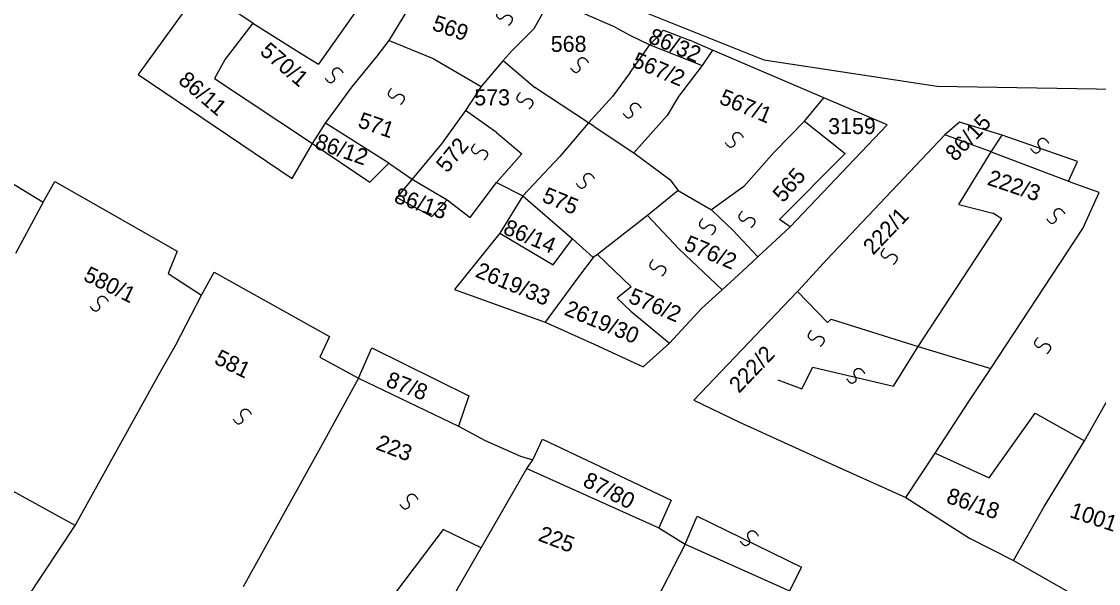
# Model space of a CAD drawing. Extents: x -581999 to -572728, y -1219553 to -1212032.
# Drawn here: x -578208.2 to -578073.6, y -1215797.5 to -1215727.3 of the extents above; entities that cross this region are included whole.
import ezdxf

# ---------------------------------------------------------------- set-up
doc = ezdxf.new("R2010")
doc.units = 0
for name, color, linetype in [('Vrstva 1', 7, 'Continuous'), ('Vrstva 2', 7, 'Continuous'), ('Vrstva 4', 7, 'Continuous'), ('Vrstva 6', 7, 'Continuous')]:
    doc.layers.add(name, color=color, linetype=linetype)

msp = doc.modelspace()

# ---------------------------------------------------------------- linework, layer by layer
at = {"layer": 'Vrstva 1'}
for p, q in [((-578129.628, -1215730.267), (-578123.109, -1215732.832)), ((-578110.331, -1215739.79), (-578105.22, -1215743.817)), ((-578090.935, -1215739.913), (-578092.767, -1215741.49)), ((-578085.613, -1215741.548), (-578090.935, -1215739.913)), ((-578086.985, -1215743.633), (-578085.613, -1215741.548)), ((-578105.22, -1215743.817), (-578113.434, -1215752.056)), ((-578086.985, -1215743.633), (-578077.316, -1215747.275)), ((-578159.362, -1215747.04), (-578161.259, -1215749.31)), ((-578077.005, -1215747.454), (-578077.316, -1215747.275)), ((-578073.5, -1215748.699), (-578077.005, -1215747.454)), ((-578161.259, -1215749.31), (-578156.879, -1215751.69)), ((-578156.879, -1215751.69), (-578154.984, -1215749.617)), ((-578112.091, -1215752.975), (-578113.434, -1215752.056)), ((-578141.728, -1215757.732), (-578139.322, -1215754.499)), ((-578120.615, -1215760.835), (-578118.072, -1215758.514)), ((-578123.156, -1215763.155), (-578120.615, -1215760.835))]:
    msp.add_line(p, q, dxfattribs=at)
for points in [[(-578162.225, -1215729.695), (-578156.331, -1215720.016), (-578155.486, -1215718.447)], [(-578162.583, -1215720.673), (-578171.062, -1215732.648)], [(-578185.669, -1215723.015), (-578193.603, -1215733.96), (-578174.349, -1215746.938), (-578171.804, -1215742.588)], [(-578137.475, -1215723.258), (-578115.402, -1215732.134), (-578093.726, -1215735.415), (-578046.398, -1215736.187), (-578004.439, -1215735.994)], [(-578142.053, -1215724.498), (-578144.151, -1215728.248)], [(-578133.982, -1215728.039), (-578142.053, -1215724.498)], [(-578179.251, -1215727.542), (-578182.684, -1215725.277)], [(-578179.251, -1215727.542), (-578182.693, -1215732.039)], [(-578179.251, -1215727.542), (-578173.1, -1215731.412)], [(-578144.151, -1215728.248), (-578146.843, -1215730.943)], [(-578133.982, -1215728.039), (-578132.14, -1215729.047)], [(-578129.628, -1215730.267), (-578127.922, -1215728.4), (-578124.701, -1215729.677)], [(-578163.722, -1215731.645), (-578162.225, -1215729.695)], [(-578162.225, -1215729.695), (-578156.702, -1215731.966)], [(-578132.14, -1215729.047), (-578129.628, -1215730.267)], [(-578121.829, -1215730.932), (-578124.701, -1215729.677)], [(-578173.1, -1215731.412), (-578171.062, -1215732.648)], [(-578146.843, -1215730.943), (-578147.987, -1215732.225)], [(-578132.109, -1215733.702), (-578129.628, -1215730.267)], [(-578121.829, -1215730.932), (-578123.109, -1215732.832), (-578126.068, -1215736.713)], [(-578107.882, -1215736.864), (-578121.829, -1215730.932)], [(-578182.693, -1215732.039), (-578184.042, -1215734.439), (-578171.804, -1215742.588)], [(-578166.865, -1215735.542), (-578163.722, -1215731.645)], [(-578156.702, -1215731.966), (-578150.733, -1215735.439)], [(-578147.987, -1215732.225), (-578150.733, -1215735.439)], [(-578147.987, -1215732.225), (-578144.017, -1215735.57)], [(-578132.109, -1215733.702), (-578134.309, -1215736.689)], [(-578150.733, -1215735.439), (-578152.68, -1215738.437)], [(-578170.157, -1215740.039), (-578166.865, -1215735.542)], [(-578137.3, -1215739.985), (-578144.017, -1215735.57)], [(-578134.309, -1215736.689), (-578137.3, -1215739.985)], [(-578126.068, -1215736.713), (-578127.498, -1215739.067)], [(-578114.109, -1215743.664), (-578110.331, -1215739.79), (-578107.882, -1215736.864)], [(-578112.091, -1215752.975), (-578099.977, -1215740.245), (-578107.882, -1215736.864)], [(-578152.68, -1215738.437), (-578155.673, -1215742.635)], [(-578148.791, -1215741.221), (-578152.68, -1215738.437)], [(-578127.498, -1215739.067), (-578131.633, -1215743.757)], [(-578171.804, -1215742.588), (-578170.157, -1215740.039)], [(-578162.248, -1215745.019), (-578170.157, -1215740.039)], [(-578137.3, -1215739.985), (-578140.891, -1215744.18)], [(-578136.603, -1215740.448), (-578137.3, -1215739.985)], [(-578136.603, -1215740.448), (-578131.633, -1215743.757)], [(-578148.791, -1215741.221), (-578145.636, -1215743.845), (-578148.811, -1215747.462)], [(-578092.767, -1215741.49), (-578107.532, -1215757.067)], [(-578086.985, -1215743.633), (-578092.767, -1215741.49)], [(-578171.804, -1215742.588), (-578164.642, -1215747.416), (-578162.248, -1215745.019)], [(-578155.673, -1215742.635), (-578159.362, -1215747.04)], [(-578140.891, -1215744.18), (-578145.528, -1215749.124)], [(-578131.633, -1215743.757), (-578127.159, -1215747.075)], [(-578117.886, -1215747.959), (-578114.109, -1215743.664)], [(-578091.025, -1215750.209), (-578086.985, -1215743.633)], [(-578162.248, -1215745.019), (-578159.362, -1215747.04)], [(-578209.608, -1215747.342), (-578205.477, -1215749.921)], [(-578205.477, -1215749.921), (-578203.992, -1215747.315), (-578188.712, -1215756.026), (-578189.828, -1215758.818)], [(-578159.362, -1215747.04), (-578154.984, -1215749.617)], [(-578154.984, -1215749.617), (-578152.104, -1215751.809), (-578148.811, -1215747.462)], [(-578148.811, -1215747.462), (-578145.528, -1215749.124)], [(-578127.159, -1215747.075), (-578126.116, -1215748.429)], [(-578126.116, -1215748.429), (-578129.943, -1215751.552)], [(-578126.116, -1215748.429), (-578121.94, -1215750.844)], [(-578117.886, -1215747.959), (-578121.94, -1215750.844)], [(-578075.523, -1215753.171), (-578073.5, -1215748.699)], [(-578205.477, -1215749.921), (-578208.899, -1215756.332)], [(-578145.528, -1215749.124), (-578148.373, -1215753.772)], [(-578145.528, -1215749.124), (-578139.322, -1215754.499)], [(-578091.025, -1215750.209), (-578086.77, -1215751.261)], [(-578129.943, -1215751.552), (-578136.166, -1215756.456)], [(-578129.943, -1215751.552), (-578125.976, -1215755.767)], [(-578121.94, -1215750.844), (-578120.918, -1215751.873), (-578119.257, -1215753.404)], [(-578096.093, -1215767.928), (-578085.677, -1215751.998), (-578086.77, -1215751.261)], [(-578148.373, -1215753.772), (-578154.058, -1215760.814), (-578142.717, -1215764.902)], [(-578148.373, -1215753.772), (-578141.728, -1215757.732)], [(-578119.257, -1215753.404), (-578116.128, -1215756.717)], [(-578116.128, -1215756.717), (-578112.091, -1215752.975)], [(-578087.045, -1215770.696), (-578075.523, -1215753.171)], [(-578139.322, -1215754.499), (-578136.731, -1215756.809)], [(-578136.731, -1215756.809), (-578138.687, -1215759.39)], [(-578136.166, -1215756.456), (-578136.731, -1215756.809)], [(-578136.166, -1215756.456), (-578131.996, -1215760.466)], [(-578125.976, -1215755.767), (-578120.615, -1215760.835)], [(-578118.072, -1215758.514), (-578116.128, -1215756.717)], [(-578107.532, -1215757.067), (-578111.047, -1215760.939), (-578111.189, -1215761.059)], [(-578189.828, -1215758.818), (-578185.661, -1215761.533)], [(-578185.661, -1215761.533), (-578184.082, -1215758.648), (-578169.672, -1215766.68), (-578170.88, -1215769.284)], [(-578138.687, -1215759.39), (-578142.717, -1215764.902)], [(-578131.996, -1215760.466), (-578133.73, -1215761.897), (-578131.999, -1215763.524)], [(-578188.879, -1215767.722), (-578185.661, -1215761.533)], [(-578111.189, -1215761.059), (-578111.331, -1215761.179), (-578124.14, -1215774.645)], [(-578111.189, -1215761.059), (-578107.428, -1215764.935)], [(-578131.999, -1215763.524), (-578127.194, -1215767.498)], [(-578127.194, -1215767.498), (-578123.156, -1215763.155)], [(-578075.317, -1215779.719), (-578066.078, -1215763.337)], [(-578142.717, -1215764.902), (-578136.599, -1215767.622)], [(-578107.428, -1215764.935), (-578106.996, -1215764.52)], [(-578106.996, -1215764.52), (-578096.093, -1215767.928)], [(-578190.884, -1215771.226), (-578188.879, -1215767.722)], [(-578136.599, -1215767.622), (-578130.483, -1215770.492), (-578127.194, -1215767.498)], [(-578166.066, -1215771.907), (-578164.393, -1215768.092), (-578152.268, -1215774.088), (-578153.57, -1215777.903)], [(-578096.093, -1215767.928), (-578087.045, -1215770.696)], [(-578170.88, -1215769.284), (-578166.066, -1215771.907)], [(-578201.443, -1215790.286), (-578190.884, -1215771.226)], [(-578089.684, -1215774.658), (-578087.045, -1215770.696)], [(-578166.066, -1215771.907), (-578170.788, -1215780.545)], [(-578166.066, -1215771.907), (-578153.57, -1215777.903)], [(-578124.14, -1215774.645), (-578118.443, -1215777.395)], [(-578093.993, -1215781.263), (-578089.684, -1215774.658)], [(-578087.231, -1215784.332), (-578081.51, -1215776.243), (-578075.317, -1215779.719)], [(-578153.57, -1215777.903), (-578150.239, -1215779.682)], [(-578118.443, -1215777.395), (-578106.348, -1215782.898)], [(-578150.239, -1215779.682), (-578145.803, -1215781.619)], [(-578144.257, -1215782.092), (-578143.048, -1215779.487), (-578126.996, -1215787.118)], [(-578080.418, -1215787.996), (-578075.317, -1215779.719)], [(-578170.788, -1215780.545), (-578180.468, -1215797.94)], [(-578145.803, -1215781.619), (-578144.257, -1215782.092)], [(-578144.995, -1215783.171), (-578144.257, -1215782.092)], [(-578097.674, -1215786.804), (-578093.993, -1215781.263)], [(-578093.993, -1215781.263), (-578087.231, -1215784.332)], [(-578150.734, -1215793.081), (-578144.995, -1215783.171)], [(-578144.995, -1215783.171), (-578128.523, -1215790.6), (-578125.238, -1215792.614)], [(-578106.348, -1215782.898), (-578097.674, -1215786.804)], [(-578201.443, -1215790.286), (-578210.075, -1215785.563), (-578215.455, -1215788.156), (-578220.697, -1215797.517)], [(-578126.996, -1215787.118), (-578128.523, -1215790.6)], [(-578097.674, -1215786.804), (-578089.703, -1215791.852)], [(-578084.212, -1215794.651), (-578080.418, -1215787.996)], [(-578231.766, -1215836.027), (-578201.443, -1215790.286)], [(-578155.491, -1215790.809), (-578166.223, -1215805.007)], [(-578150.734, -1215793.081), (-578155.491, -1215790.809)], [(-578089.703, -1215791.852), (-578084.212, -1215794.651)], [(-578159.75, -1215808.746), (-578150.734, -1215793.081)], [(-578125.238, -1215792.614), (-578130.145, -1215802.172), (-578130.44, -1215802.654)], [(-578125.238, -1215792.614), (-578112.187, -1215798.456)], [(-578084.212, -1215794.651), (-578074.129, -1215800.41)]]:
    msp.add_lwpolyline(points, dxfattribs=at)
at = {"layer": 'Vrstva 4'}
for p, q in [((-578076.21, -1215744.81), (-578085.613, -1215741.548)), ((-578077.316, -1215747.275), (-578076.21, -1215744.81)), ((-578125.238, -1215792.614), (-578123.711, -1215789.132))]:
    msp.add_line(p, q, dxfattribs=at)
for points in [[(-578110.63, -1215773.209), (-578109.289, -1215770.522), (-578099.206, -1215772.873), (-578096.093, -1215767.928)], [(-578113.667, -1215772.099), (-578110.63, -1215773.209)], [(-578123.711, -1215789.132), (-578110.701, -1215795.48), (-578112.187, -1215798.456)]]:
    msp.add_lwpolyline(points, dxfattribs=at)
at = {"layer": 'Vrstva 6'}
for points in [[(-578148.405, -1215725.77), (-578148.992, -1215726.392), (-578148.537, -1215727.001), (-578148.131, -1215726.989), (-578147.845, -1215726.684), (-578147.539, -1215726.53), (-578147.239, -1215726.546), (-578147.032, -1215726.648), (-578146.856, -1215726.851), (-578146.811, -1215727.215), (-578147.146, -1215727.727), (-578147.304, -1215727.819)], [(-578139.568, -1215733.114), (-578139.088, -1215733.821), (-578138.394, -1215733.51), (-578138.317, -1215733.11), (-578138.553, -1215732.765), (-578138.638, -1215732.433), (-578138.556, -1215732.143), (-578138.412, -1215731.963), (-578138.176, -1215731.835), (-578137.811, -1215731.871), (-578137.384, -1215732.31), (-578137.329, -1215732.483)], [(-578170.234, -1215734.395), (-578169.754, -1215735.102), (-578169.06, -1215734.791), (-578168.983, -1215734.391), (-578169.219, -1215734.046), (-578169.304, -1215733.714), (-578169.222, -1215733.424), (-578169.078, -1215733.244), (-578168.842, -1215733.116), (-578168.477, -1215733.152), (-578168.05, -1215733.591), (-578167.995, -1215733.764)], [(-578161.913, -1215735.656), (-578162.5, -1215736.278), (-578162.045, -1215736.887), (-578161.639, -1215736.875), (-578161.353, -1215736.57), (-578161.047, -1215736.416), (-578160.747, -1215736.432), (-578160.54, -1215736.534), (-578160.364, -1215736.737), (-578160.319, -1215737.101), (-578160.654, -1215737.613), (-578160.812, -1215737.705)], [(-578145.849, -1215736.205), (-578146.436, -1215736.827), (-578145.981, -1215737.436), (-578145.575, -1215737.424), (-578145.289, -1215737.119), (-578144.983, -1215736.965), (-578144.683, -1215736.981), (-578144.476, -1215737.083), (-578144.3, -1215737.286), (-578144.255, -1215737.65), (-578144.59, -1215738.162), (-578144.748, -1215738.254)], [(-578132.996, -1215738.789), (-578132.516, -1215739.496), (-578131.822, -1215739.185), (-578131.745, -1215738.785), (-578131.981, -1215738.44), (-578132.066, -1215738.108), (-578131.984, -1215737.818), (-578131.84, -1215737.638), (-578131.604, -1215737.51), (-578131.239, -1215737.546), (-578130.812, -1215737.985), (-578130.757, -1215738.158)], [(-578120.219, -1215742.451), (-578119.739, -1215743.158), (-578119.045, -1215742.847), (-578118.968, -1215742.447), (-578119.204, -1215742.102), (-578119.289, -1215741.77), (-578119.207, -1215741.48), (-578119.063, -1215741.3), (-578118.827, -1215741.172), (-578118.462, -1215741.208), (-578118.035, -1215741.647), (-578117.98, -1215741.82)], [(-578082.068, -1215743.183), (-578081.588, -1215743.89), (-578080.894, -1215743.579), (-578080.817, -1215743.179), (-578081.053, -1215742.834), (-578081.138, -1215742.502), (-578081.056, -1215742.212), (-578080.912, -1215742.032), (-578080.676, -1215741.904), (-578080.311, -1215741.94), (-578079.884, -1215742.379), (-578079.829, -1215742.552)], [(-578151.508, -1215742.613), (-578152.095, -1215743.235), (-578151.64, -1215743.844), (-578151.234, -1215743.832), (-578150.948, -1215743.527), (-578150.642, -1215743.373), (-578150.342, -1215743.389), (-578150.135, -1215743.491), (-578149.959, -1215743.694), (-578149.914, -1215744.058), (-578150.249, -1215744.57), (-578150.407, -1215744.662)], [(-578138.838, -1215747.578), (-578138.358, -1215748.285), (-578137.664, -1215747.974), (-578137.587, -1215747.574), (-578137.823, -1215747.229), (-578137.908, -1215746.897), (-578137.826, -1215746.607), (-578137.682, -1215746.427), (-578137.446, -1215746.299), (-578137.081, -1215746.335), (-578136.654, -1215746.774), (-578136.599, -1215746.947)], [(-578118.104, -1215751.035), (-578118.691, -1215751.657), (-578118.236, -1215752.266), (-578117.83, -1215752.254), (-578117.544, -1215751.949), (-578117.238, -1215751.795), (-578116.938, -1215751.811), (-578116.731, -1215751.913), (-578116.555, -1215752.116), (-578116.51, -1215752.48), (-578116.845, -1215752.992), (-578117.003, -1215753.084)], [(-578080.06, -1215751.972), (-578079.58, -1215752.679), (-578078.886, -1215752.368), (-578078.809, -1215751.968), (-578079.045, -1215751.623), (-578079.13, -1215751.291), (-578079.048, -1215751.001), (-578078.904, -1215750.821), (-578078.668, -1215750.693), (-578078.303, -1215750.729), (-578077.876, -1215751.168), (-578077.821, -1215751.341)], [(-578123.032, -1215751.951), (-578123.619, -1215752.573), (-578123.164, -1215753.182), (-578122.758, -1215753.17), (-578122.472, -1215752.865), (-578122.166, -1215752.711), (-578121.866, -1215752.727), (-578121.659, -1215752.829), (-578121.483, -1215753.032), (-578121.438, -1215753.396), (-578121.773, -1215753.908), (-578121.931, -1215754)], [(-578100.322, -1215755.638), (-578100.909, -1215756.26), (-578100.454, -1215756.869), (-578100.048, -1215756.857), (-578099.762, -1215756.552), (-578099.456, -1215756.398), (-578099.156, -1215756.414), (-578098.949, -1215756.516), (-578098.773, -1215756.719), (-578098.728, -1215757.083), (-578099.063, -1215757.595), (-578099.221, -1215757.687)], [(-578129.238, -1215757.077), (-578129.825, -1215757.699), (-578129.37, -1215758.308), (-578128.964, -1215758.296), (-578128.678, -1215757.991), (-578128.372, -1215757.837), (-578128.072, -1215757.853), (-578127.865, -1215757.955), (-578127.689, -1215758.158), (-578127.644, -1215758.522), (-578127.979, -1215759.034), (-578128.137, -1215759.126)], [(-578199.592, -1215762.914), (-578199.112, -1215763.621), (-578198.418, -1215763.31), (-578198.341, -1215762.91), (-578198.577, -1215762.565), (-578198.662, -1215762.233), (-578198.58, -1215761.943), (-578198.436, -1215761.763), (-578198.2, -1215761.635), (-578197.835, -1215761.671), (-578197.408, -1215762.11), (-578197.353, -1215762.283)], [(-578109.449, -1215765.891), (-578110.036, -1215766.513), (-578109.581, -1215767.122), (-578109.175, -1215767.11), (-578108.889, -1215766.805), (-578108.583, -1215766.651), (-578108.283, -1215766.667), (-578108.076, -1215766.769), (-578107.9, -1215766.972), (-578107.855, -1215767.336), (-578108.19, -1215767.848), (-578108.348, -1215767.94)], [(-578081.155, -1215766.807), (-578081.742, -1215767.429), (-578081.287, -1215768.038), (-578080.881, -1215768.026), (-578080.595, -1215767.721), (-578080.289, -1215767.567), (-578079.989, -1215767.583), (-578079.782, -1215767.685), (-578079.606, -1215767.888), (-578079.561, -1215768.252), (-578079.896, -1215768.764), (-578080.054, -1215768.856)], [(-578105.068, -1215771.928), (-578104.588, -1215772.635), (-578103.894, -1215772.324), (-578103.817, -1215771.924), (-578104.053, -1215771.579), (-578104.138, -1215771.247), (-578104.056, -1215770.957), (-578103.912, -1215770.777), (-578103.676, -1215770.649), (-578103.311, -1215770.685), (-578102.884, -1215771.124), (-578102.829, -1215771.297)], [(-578181.703, -1215777.012), (-578181.223, -1215777.719), (-578180.529, -1215777.408), (-578180.452, -1215777.008), (-578180.688, -1215776.663), (-578180.773, -1215776.331), (-578180.691, -1215776.041), (-578180.547, -1215775.861), (-578180.311, -1215775.733), (-578179.946, -1215775.769), (-578179.519, -1215776.208), (-578179.464, -1215776.381)], [(-578160.894, -1215787.631), (-578160.414, -1215788.338), (-578159.72, -1215788.027), (-578159.643, -1215787.627), (-578159.879, -1215787.282), (-578159.964, -1215786.95), (-578159.882, -1215786.66), (-578159.738, -1215786.48), (-578159.502, -1215786.352), (-578159.137, -1215786.388), (-578158.71, -1215786.827), (-578158.655, -1215787)], [(-578118.363, -1215792.209), (-578117.883, -1215792.916), (-578117.189, -1215792.605), (-578117.112, -1215792.205), (-578117.348, -1215791.86), (-578117.433, -1215791.528), (-578117.351, -1215791.238), (-578117.207, -1215791.058), (-578116.971, -1215790.93), (-578116.606, -1215790.966), (-578116.179, -1215791.405), (-578116.124, -1215791.578)]]:
    msp.add_open_spline(points, degree=2, dxfattribs=at)

# ---------------------------------------------------------------- texts
at = {"layer": 'Vrstva 2'}
for s, rotation, p in [('569', 340.89447, (-578156.977, -1215728.354)), ('86/32', 337.42286, (-578129.981, -1215729.923)), ('570/1', 319.39329, (-578178.492, -1215731.271)), ('567/2', 337.42286, (-578131.994, -1215732.918)), ('86/11', 319.39329, (-578188.7, -1215734.904)), ('567/1', 337.42286, (-578121.11, -1215737.532)), ('571', 340.89447, (-578166.261, -1215740.483)), ('86/15', 46.29628, (-578091.474, -1215744.925)), ('86/12', 340.89447, (-578171.65, -1215743.146)), ('572', 50.91679, (-578154.975, -1215746.357)), ('565', 48.53983, (-578112.983, -1215750.066)), ('222/3', 341.38126, (-578087.599, -1215747.689)), ('86/13', 340.89447, (-578161.735, -1215749.892)), ('575', 337.42286, (-578143.238, -1215749.792)), ('222/1', 46.29628, (-578101.754, -1215756.603)), ('86/14', 337.42286, (-578148.108, -1215753.807)), ('576/2', 337.42286, (-578125.517, -1215755.798)), ('580/1', 333.83334, (-578200.561, -1215759.61)), ('2619/33', 337.42286, (-578151.574, -1215759.176)), ('576/2', 337.42286, (-578132.453, -1215762.389)), ('2619/30', 337.42286, (-578140.463, -1215763.928)), ('581', 333.83334, (-578184.207, -1215770.005)), ('222/2', 46.29628, (-578118.505, -1215773.86)), ('87/8', 339.1344, (-578162.762, -1215772.855)), ('223', 339.1344, (-578164.012, -1215780.732)), ('87/80', 333.12485, (-578138.164, -1215785.286)), ('86/18', 341.38126, (-578092.729, -1215787.409)), ('1001', 341.38126, (-578077.298, -1215789.209)), ('225', 339.1344, (-578143.725, -1215792.138))]:
    msp.add_text(s, height=2, rotation=rotation, dxfattribs=at).set_placement(p)
for s, p in [('568', (-578142.023, -1215731.133)), ('573', (-578151.585, -1215737.809)), ('3159', (-578107.357, -1215741.398))]:
    msp.add_text(s, height=2, dxfattribs=at).set_placement(p)

doc.saveas('drawing.dxf')
